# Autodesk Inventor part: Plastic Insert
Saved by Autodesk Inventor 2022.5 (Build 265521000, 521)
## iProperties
Created: 2025-02
Part Number: Plastic Insert
Material: Generic
Document SubType Name: Modeling
Designer: AdminForWorker
Density: 1 g/cm^3
Appearance: Default
Title: Plastic Insert
Author: AdminForWorker
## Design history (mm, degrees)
feature "Plastic Insert"
body "Solid1"
